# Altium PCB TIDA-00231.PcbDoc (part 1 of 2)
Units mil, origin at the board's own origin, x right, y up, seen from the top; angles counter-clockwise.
Board outline 3780 x 2000 mil, 4 copper layers (Top Layer, L2_GND-PLANE, L3_PWR-PLANE, Bottom Layer), stack 90 mil thick; 180 components, 82 nets, 468 pads, 188 vias.
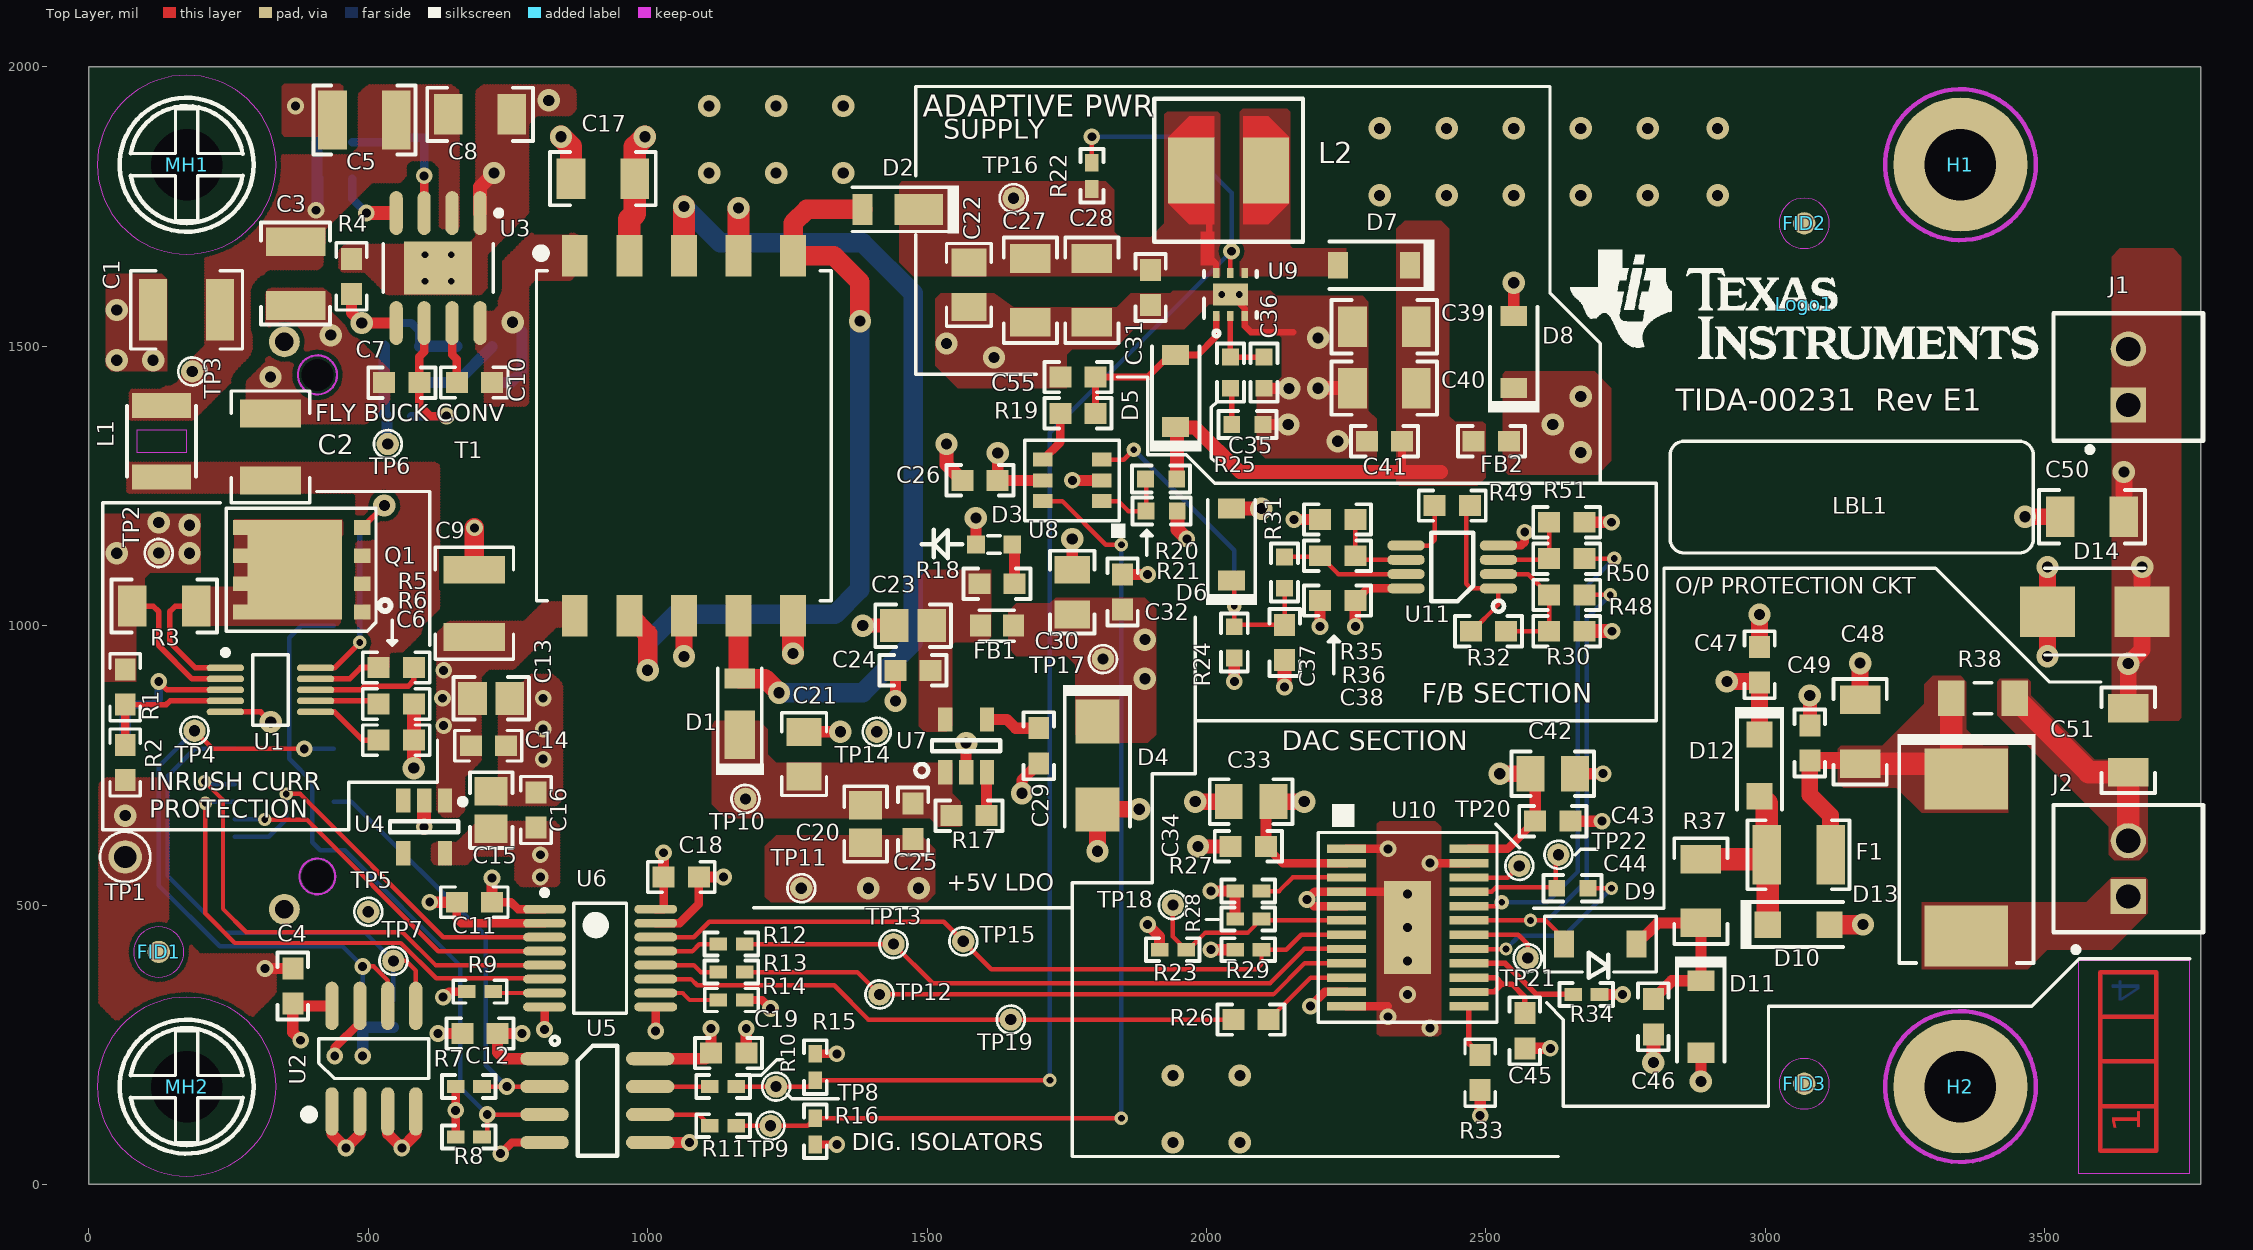
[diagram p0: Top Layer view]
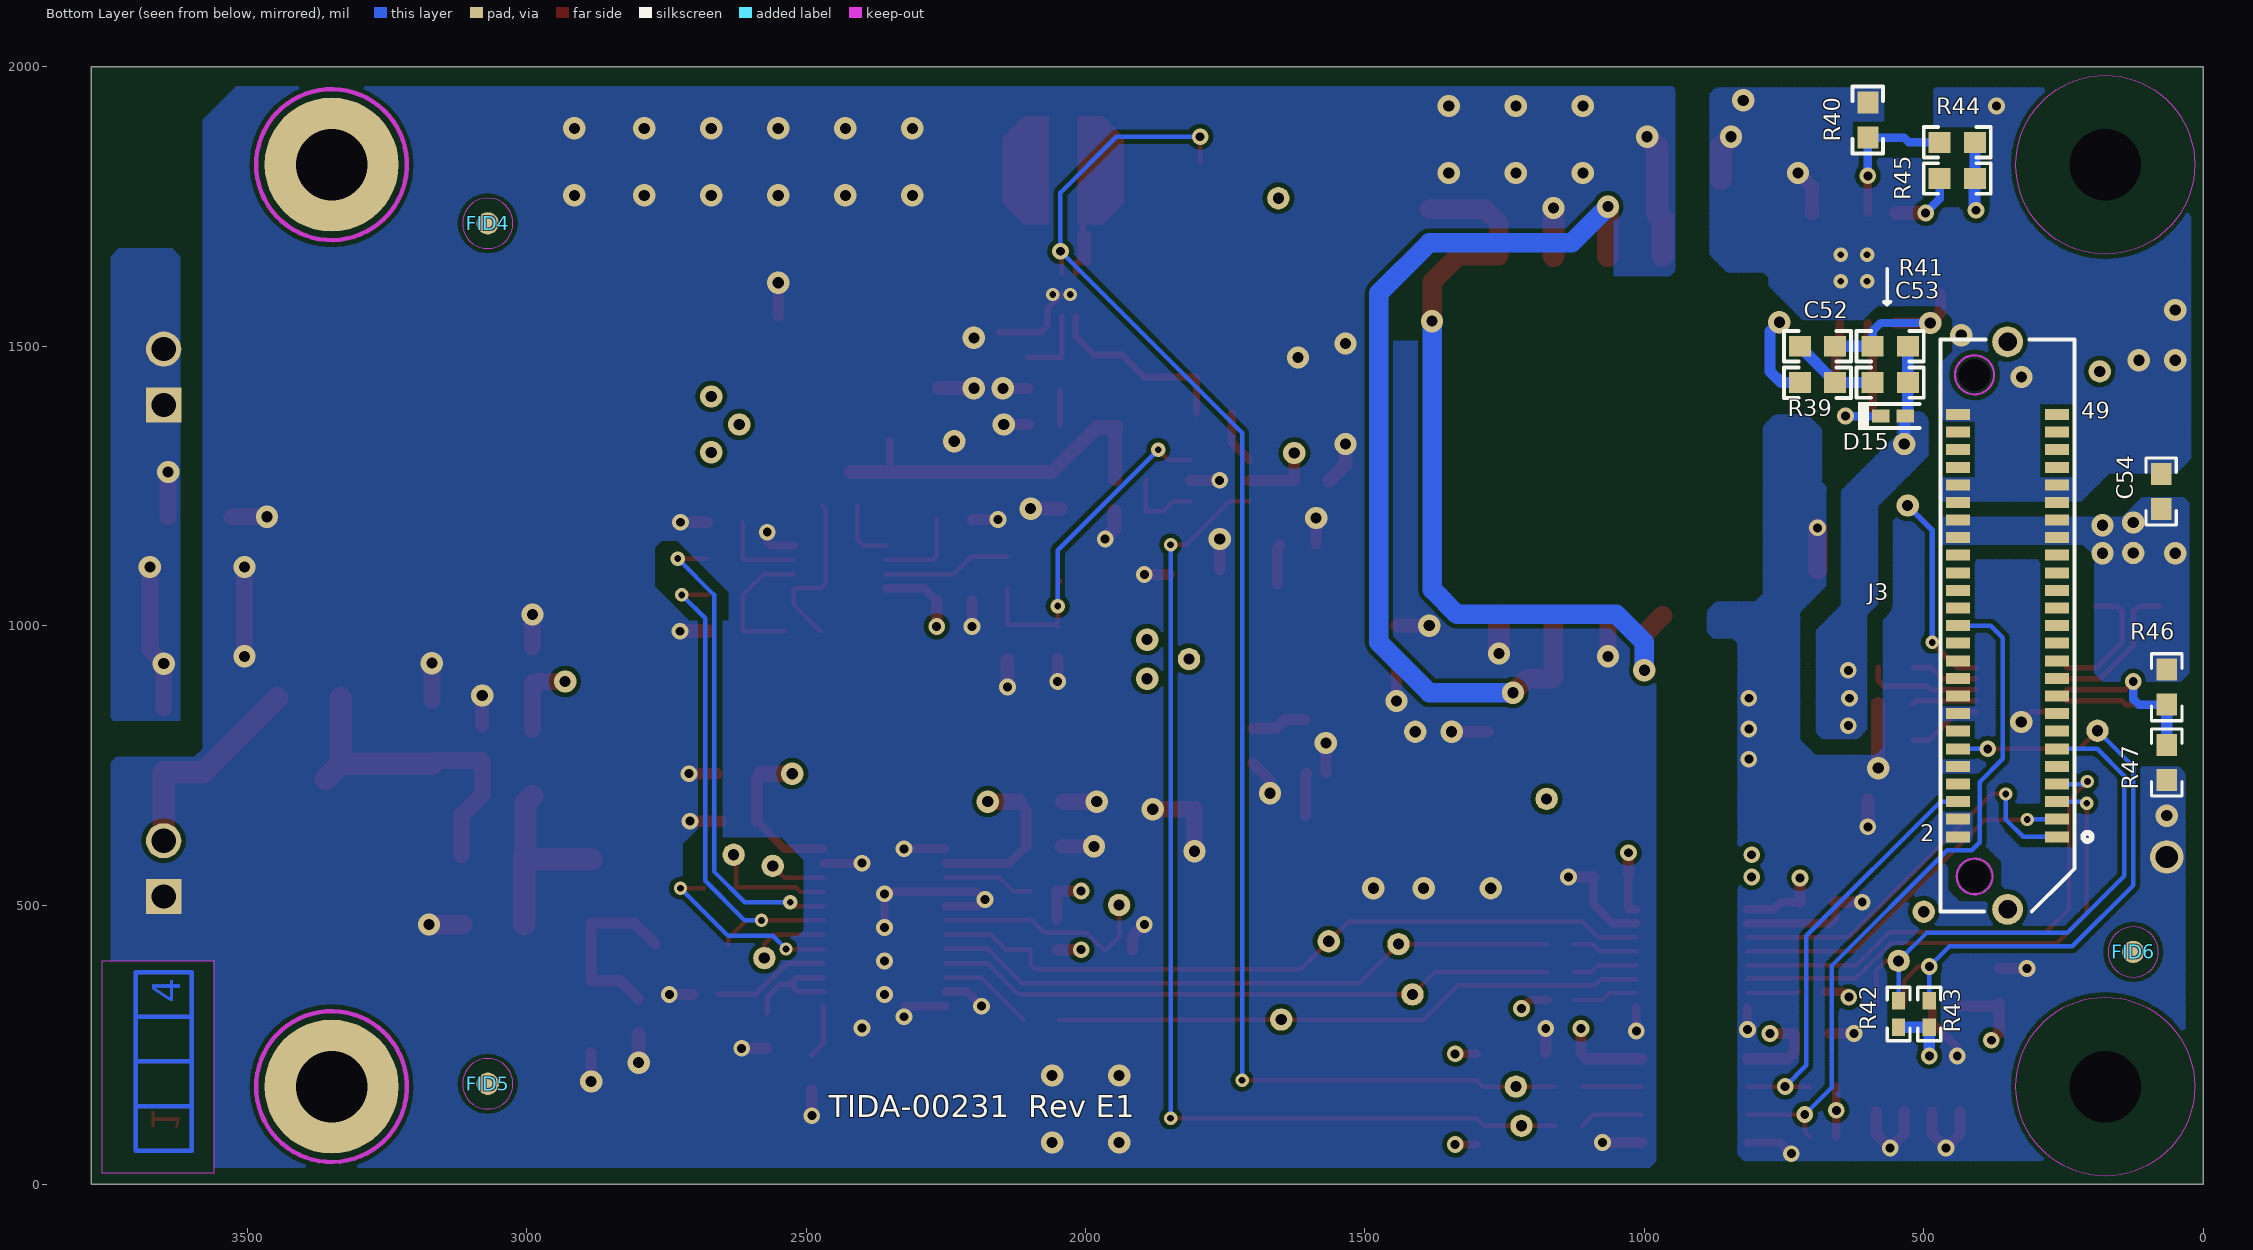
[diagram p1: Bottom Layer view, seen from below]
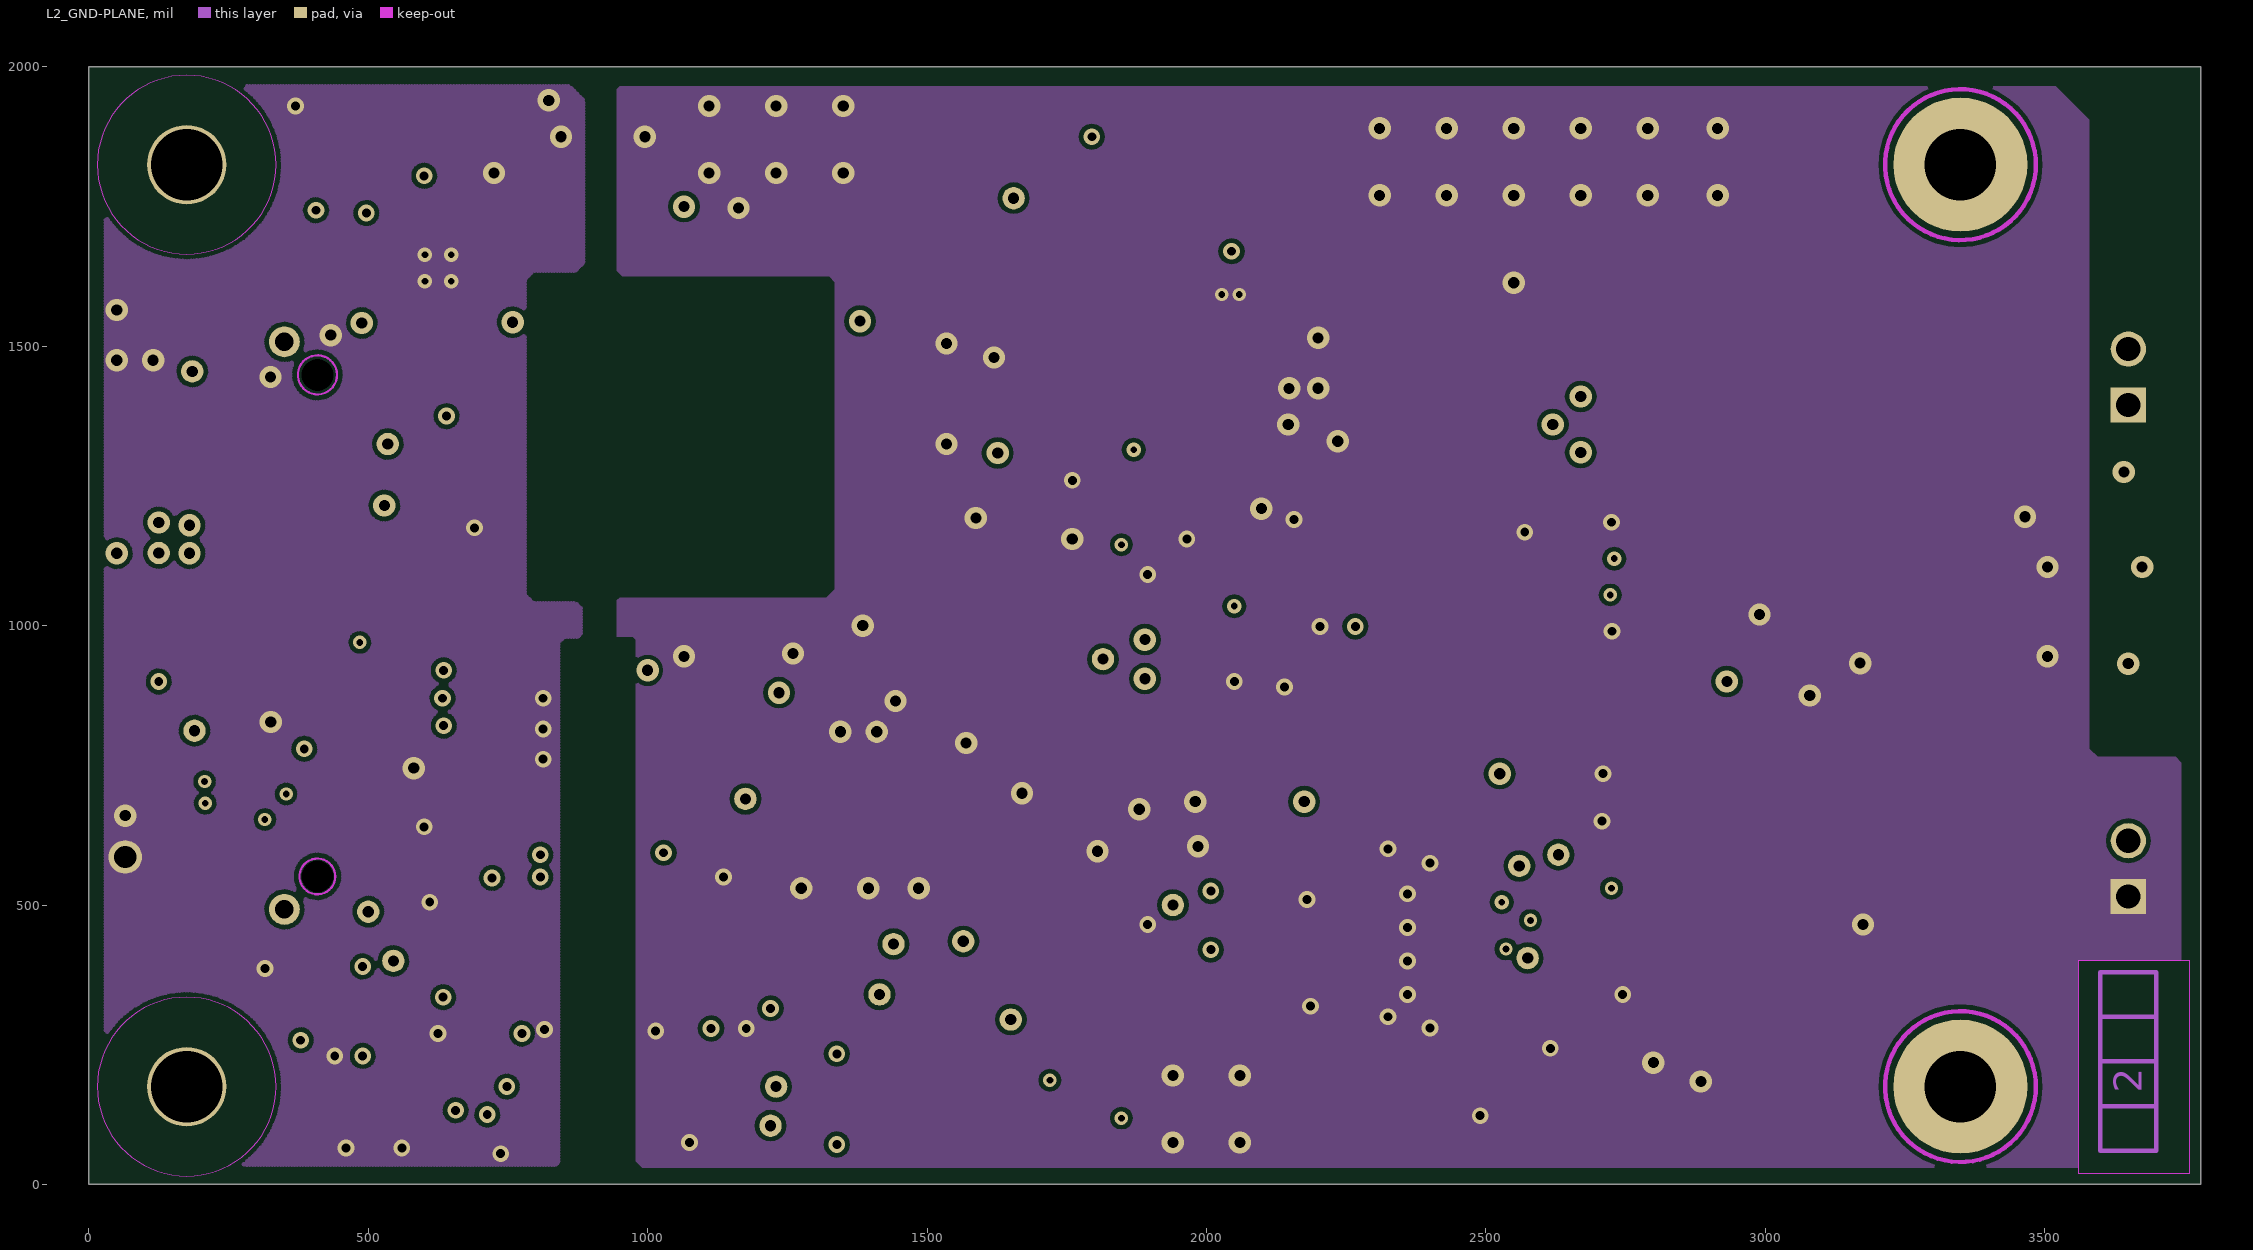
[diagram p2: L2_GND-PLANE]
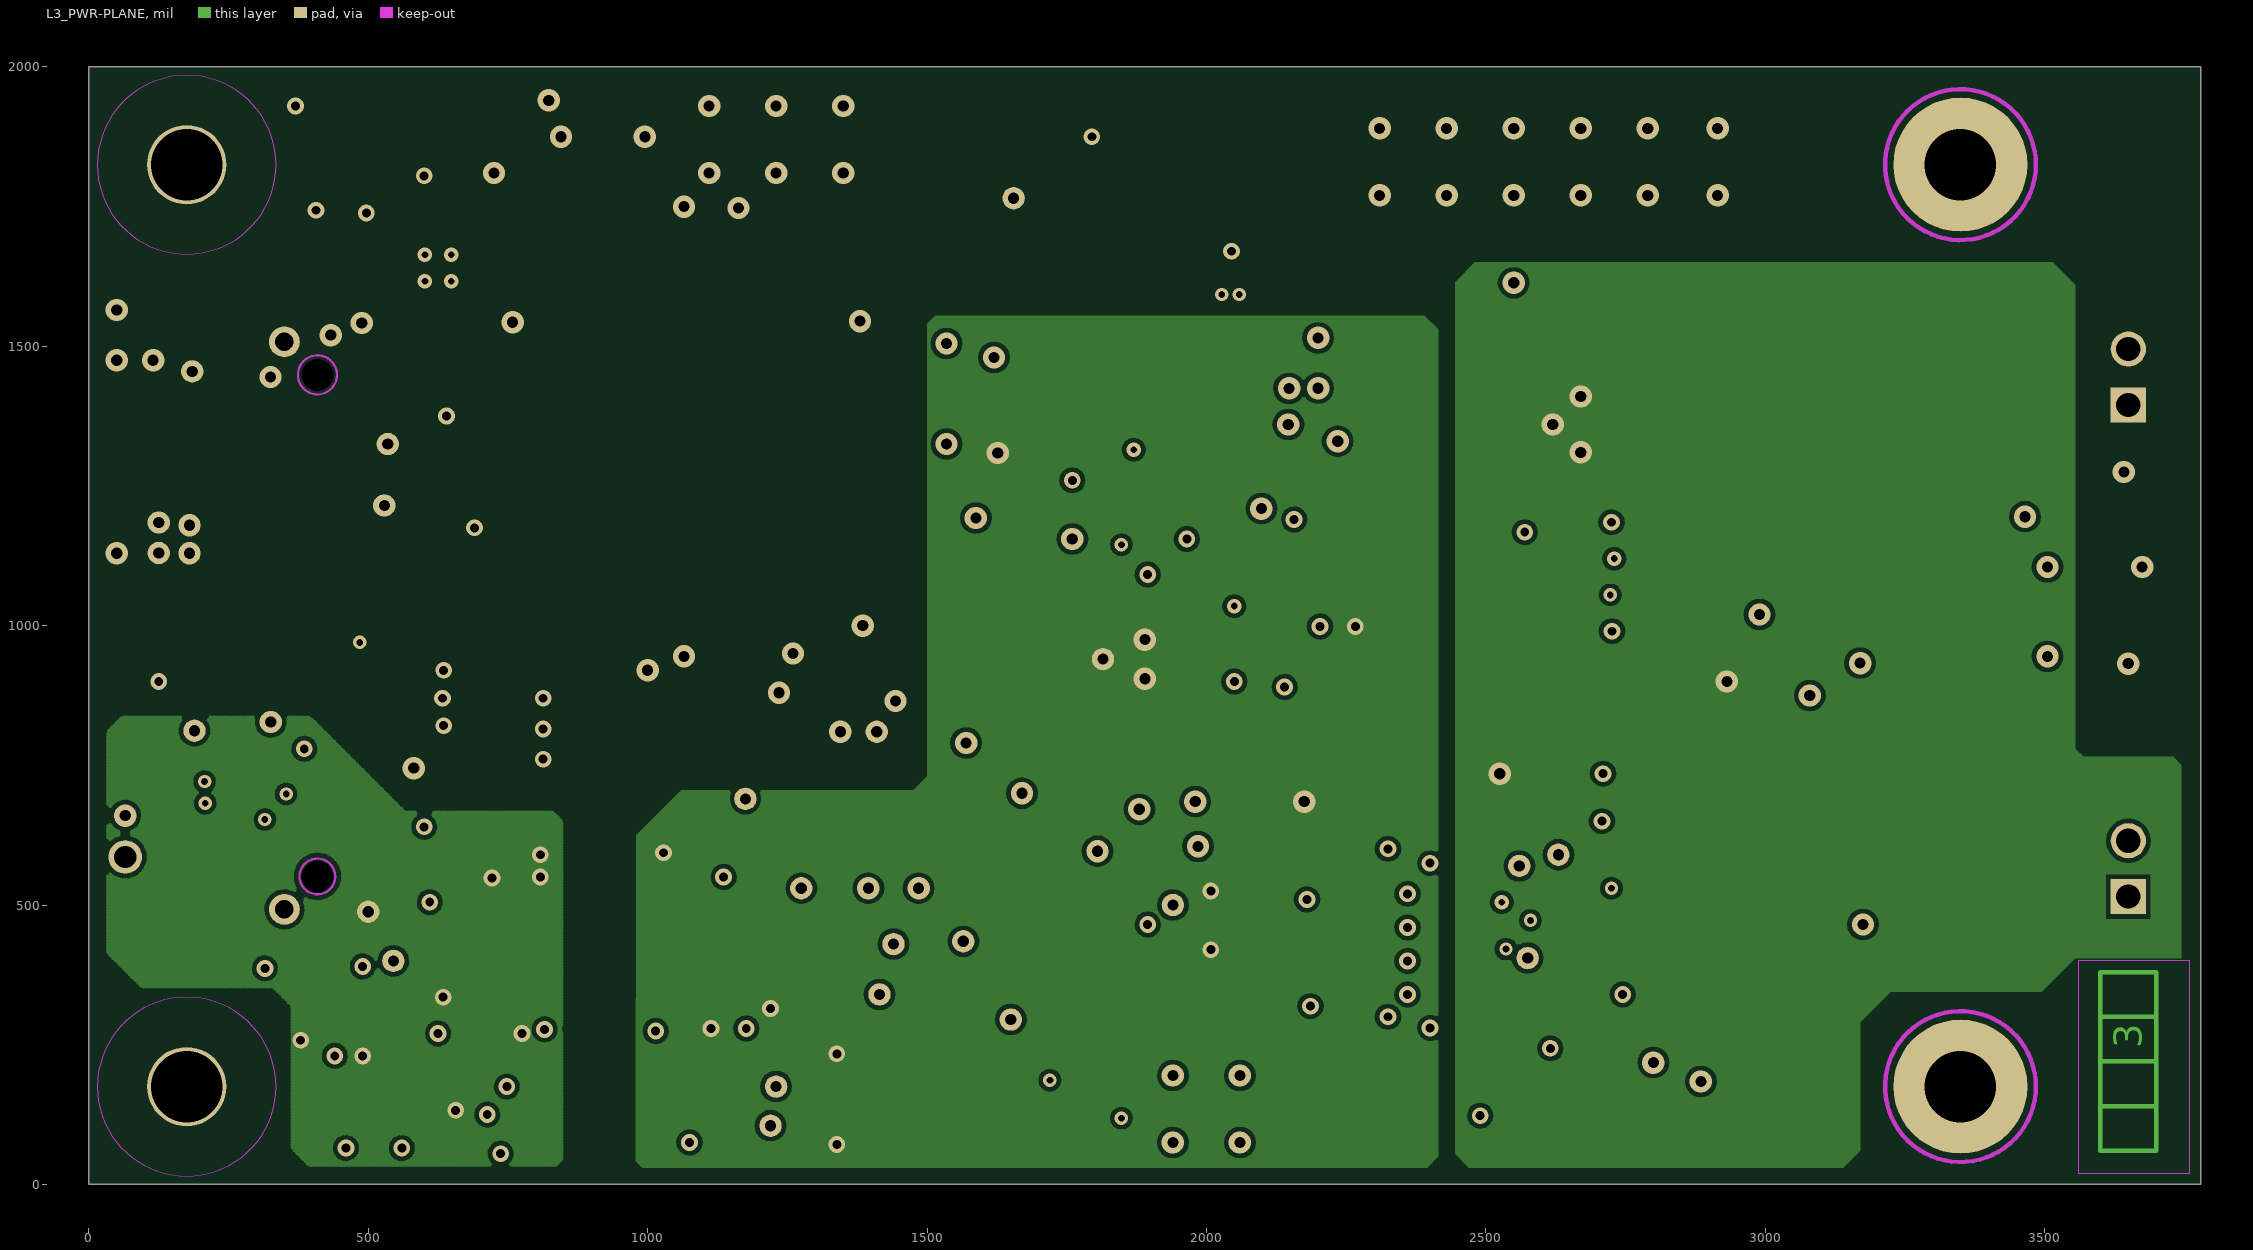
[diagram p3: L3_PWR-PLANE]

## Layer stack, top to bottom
Top Layer: signal copper 1.4
Dielectric: core 59.2, FR-4, Dk 4.8
L2_GND-PLANE: signal copper 1.4
Dielectric: prepreg 12.6, FR-4, Dk 4.8
L3_PWR-PLANE: signal copper 1.4
Dielectric: core 12.6, FR-4, Dk 4.8
Bottom Layer: signal copper 1.4

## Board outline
0,0 0,2000 3780,2000 3780,0

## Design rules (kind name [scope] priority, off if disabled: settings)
AcuteAngle [All] p1: minimum=4.50000000000000E+0001 checktracksonly=FALSE
AssemblyTestPointUsage [All] p1: valid=2
Clearance "U7 AND U9 Pad Class" [(InPadClass('Less Than 7.7')) vs (InPadClass('Less Than 7.7'))] p1: gap=7.8
Clearance "Clearance_Poly to Poly" [InPolygon vs InPolygon] p2: gap=25
Clearance "Clearance_VIA TO VIA" [IsVia vs IsVia] p3: gap=10
Clearance "Clearance_Via to SMD" [IsVia vs IsSMTPin] p4: gap=9
Clearance Clearance_Poly [InPolygon vs IsTrack and IsVia and IsSMTPin and IsThruPin] p5: gap=12
Clearance [All] p6: gap=8
ComponentClearance ComponentClearance_Logo [InComponentClass('Logo')] p1: gap=50 collisioncheckmode=3 verticalgap=10 showdistances=FALSE
ComponentClearance ComponentClearance_ScrewToNut [(HasFootprint('NY PMS 440 0025 PH')) vs (HasFootprint('Keystone_1902C'))] p2: gap=5 collisioncheckmode=3 verticalgap=10 showdistances=FALSE
ComponentClearance ComponentClearance_MountingHoles [InComponentClass('Mounting Holes')] p3: gap=250 collisioncheckmode=3 verticalgap=100000 showdistances=FALSE
ComponentClearance ComponentClearance_SmallPassives [HasFootprint('0201*') or HasFootprint('0402*') or HasFootprint('0508') or HasFootprint('0603*') or HasFootprint('0612') or HasFootprint('0805*') or HasFootprint('0815*') or HasFootprint('0830*') or HasFootprint('1206*') or HasFootprint('1210*') or HasFootprint('1808*') or HasFootprint('1812*') or HasFootprint('1825*') or HasFootprint('2010*') or HasFootprint('2220*') or HasFootprint('2225*') or HasFootprint('2512*') or HasFootprint('2728*') or HasFootprint('3518*') vs HasFootprint('0201*') or HasFootprint('0402*') or HasFootprint('0508') or HasFootprint('0603*') or HasFootprint('0612') or HasFootprint('0805*') or HasFootprint('0815*') or HasFootprint('0830*') or HasFootprint('1206*') or HasFootprint('1210*') or HasFootprint('1808*') or HasFootprint('1812*') or HasFootprint('1825*') or HasFootprint('2010*') or HasFootprint('2220*') or HasFootprint('2225*') or HasFootprint('2512*') or HasFootprint('2728*') or HasFootprint('3518*')] p4: gap=20 collisioncheckmode=3 verticalgap=10 showdistances=FALSE
ComponentClearance ComponentClearance_THtoSMT [IsThruComponent vs IsSMTComponent] p5: gap=100 collisioncheckmode=3 verticalgap=30 showdistances=FALSE
ComponentClearance ComponentClearance_THtoTH [IsThruComponent vs IsThruComponent] p6: gap=118.11 collisioncheckmode=3 verticalgap=30 showdistances=FALSE
ComponentClearance [All] p7: gap=40 collisioncheckmode=3 verticalgap=10 showdistances=FALSE
DiffPairsRouting [All] p1: maxlimit=100 minlimit=10 mostfreqgap=10 maxuncoupledlength=1000
FabricationTestPointUsage TestPointUsage [All] p1: valid=2 allowmultiple=FALSE
FabricationTestpoint Testpoint [All] p1: side=3 testpointundercomponent=TRUE minsize=40 maxsize=100 preferedsize=60 minholesize=0 maxholesize=40 preferedholesize=32 testpointgrid=1 allowsidetop=TRUE allowsidebottom=TRUE usegrid=TRUE gridtolerance=0.01
FanoutControl Fanout_LCC [IsLCC] p1: bgadir=Out bgaviamode=Centered fanoutstyle=Auto fanoutdirection=Alternating viagrid=1 // Fanout_LCC (Default Rule)
FanoutControl Fanout_BGA [IsBGA] p2: bgadir=Out bgaviamode=Centered fanoutstyle=Auto fanoutdirection=Alternating viagrid=1 // Fanout_BGA (Default Rule)
FanoutControl Fanout_Default [All] p4: bgadir=Out bgaviamode=Centered fanoutstyle=Auto fanoutdirection=Alternating viagrid=1 // Fanout_Default (Default Rule)
FanoutControl Fanout_Small [(CompPinCount < 5)] p5: bgadir=Out bgaviamode=Centered fanoutstyle=Auto fanoutdirection=OutThenIn viagrid=1 // Fanout_Small (Default Rule)
HoleSize [All] p1: absolutevalues=TRUE maxlimit=251 minlimit=7.8 maxpercent=80.000 minpercent=20.000
MinimumAnnularRing MinimumAnnularRing_ThermalPadVias [IsVia and InAnyComponent] p1: minimumring=5.91
MinimumAnnularRing [All] p2: minimumring=6
MinimumSolderMaskSliver MinimumSolderMaskSliver_Logo [InComponentClass('Logo') vs InComponentClass('Logo')] p1: minsoldermaskwidth=0.7
MinimumSolderMaskSliver [All] p2: minsoldermaskwidth=3.94
PlaneClearance [All] p1: clearance=16
PlaneConnect [All] p1: planeconnectstyle=Direct reliefexpansion=10 reliefentries=4 reliefconductorwidth=10 reliefairgap=10
PolygonConnect [All] p1: connectstyle=Direct reliefconductorwidth=10 reliefentries=4 polygonreliefangle="90 Angle" airgapwidth=10
RoutingVias RoutingVias_PWR [InNetClass('PWR')] p1: holewidth=20 width=40 viastyle="Through Hole" minholewidth=20 minwidth=40 maxholewidth=20 maxwidth=40
RoutingVias [InNetClass('All Nets')] p2: holewidth=16 width=30 viastyle="Through Hole" minholewidth=8 minwidth=20 maxholewidth=20 maxwidth=40
RoutingVias ThermalPadVias [IsVia and InAnyComponent] p3: holewidth=7.87 width=19.68 viastyle="Through Hole" minholewidth=7.87 minwidth=19.68 maxholewidth=12.99 maxwidth=23.62
SMDToCorner [All] p1: distance=30000
SilkToSilkClearance [All] p1: silktosilkclearance=5
SilkscreenOverComponentPads [All] p1 off: minsilkscreentomaskgap=5
SolderMaskExpansion [All] p1: expansion=2.5
Width Width_PWR [InNetClass('PWR')] p1: maxlimit=100 minlimit=8 preferedwidth=10
Width [All] p2: maxlimit=100 minlimit=6 preferedwidth=8 checkconnectedcopper=TRUE
13 further rules are at their usual default settings.

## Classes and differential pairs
pad class "Less Than 7.7": U1-1 U1-2 U1-3 U1-4 U1-5 U1-6 U1-7 U1-8 U1-9 U1-10 U11-1 U11-2 U11-3 U11-4 U11-5 U11-6 U11-7 U11-8
component class "Pg4 ISO Power Supply, I2C & SPI Isolators": C1 C3 C5 C7 C8 C9 C10 C11 C12 C13 C14 C15 C16 C17 C18 C19 C20 C21 C22 C23 C24 C25 C29 C30 C32 C52 C53 D1 D2 D3 D4 D15 FB1 L1 R4 R7 R8 R9 R10 R11 R12 R13 R14 R15 R16 R17 R18 R39 R40 R41 R44 R45 T1 TP3 TP5 TP6 TP8 TP9 TP10 TP11 TP14 TP16 TP17 U3 U4 U5 U6 U7
component class "Pg3 Interboard conn, HS & EEPROM": C2 C4 C6 C54 J3 Q1 R1 R2 R3 R5 R6 R42 R43 R46 R47 TP1 TP2 TP4 TP7 U1 U2
component class Logo: Logo1
component class "Pg6 Hardware": FID1 FID2 FID3 FID4 FID5 FID6 H1 H2 LBL1 Logo1 MH1 MH2 ZZ1 ZZ2 ZZ3 ZZ4
component class AssemblyNote: ZZ1 ZZ2 ZZ3 ZZ4
component class Label: LBL1
component class "Mounting Holes": H1 H2
component class "Pg5 Analog Output & Adaptive PS": C26 C27 C28 C31 C33 C34 C35 C36 C37 C38 C39 C40 C41 C42 C43 C44 C45 C46 C47 C48 C49 C50 C51 C55 D5 D6 D7 D8 D9 D10 D11 D12 D13 D14 F1 FB2 J1 J2 L2 R19 R20 R21 R22 R23 R24 R25 R26 R27 R28 R29 R30 R31 R32 R33 R34 R35 R36 R37 R38 R48 R49 R50 R51 TP12 TP13 TP15 TP18 TP19 TP20 TP21 TP22 TP39 TP40 TP41 TP42 TP43 TP44 TP46 U8 U9 U10 U11

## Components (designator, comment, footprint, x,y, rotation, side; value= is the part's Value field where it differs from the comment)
C1 "GRM32ER72A225KA35L" 1210#1 175,1565 r180 top (schematic designator C88)
C2 "GRM32ER72A225KA35L" 1210#1 325,1320 r270 top (schematic designator C44)
C3 "GRM32ER71H106KA12L" 1210#2 370,1630 r270 top (schematic designator C136)
C4 "C0603C104K5RACTU" 0603 365,355 r270 top (schematic designator C29)
C5 "GRM32ER72A225KA35L" 1210#2 493,1905 r0 top (schematic designator C10)
C6 "UMK107ABJ474KA-T" 0603 550,795 r0 top (schematic designator C78)
C7 "GRM188R61H105KAALD" 0603 560,1435 r180 top (schematic designator C8)
C8 "GRM31MR72A474KA35L" 1206 700,1915 r180 top (schematic designator C3)
C9 "GMK325AB7106MM-T" 1210#1 690,1040 r270 top (schematic designator C96)
C10 "06031C103JAT2A" 0603 690,1435 r0 top (schematic designator C4)
C11 "C0603C104K5RACTU" 0603 690,505 r0 top (schematic designator C106)
C12 "C0603C104K5RACTU" 0603 700,270 r0 top (schematic designator C133)
C13 "08055C105KAT2A" 0805 720,870 r0 top (schematic designator C17)
C14 "C0603C104K5RACTU" 0603 715,785 r0 top (schematic designator C20)
C15 "0805YD106MAT2A" 0805 720,670 r90 top (schematic designator C105)
C16 "C0603C104K5RACTU" 0603 800,670 r90 top (schematic designator C23)
C17 "202R18W102KV4E" 1206 920,1800 r0 top (schematic designator C36)
C18 "C0603C104K5RACTU" 0603 1060,550 r0 top (schematic designator C68)
C19 "C0603C104K5RACTU" 0603 1145,235 r0 top (schematic designator C134)
C20 "08055C105KAT2A" 0805 1390,645 r270 top (schematic designator C112)
C21 "GRM21BR71E225KA73L" 0805_HV 1280,770 r270 top (schematic designator C24)
C22 "GRM21BR71E225KA73L" 0805_HV 1575,1610 r270 top (schematic designator C6)
C23 "0805YD106MAT2A" 0805 1475,1000 r180 top (schematic designator C87)
C24 "C0603C104K5RACTU" 0603 1475,920 r180 top (schematic designator C18)
C25 "C0603C104K5RACTU" 0603 1475,650 r270 top (schematic designator C86)
C26 "06035C104KAT2A" 0603 1595,1260 r180 top (schematic designator C91)
C27 "GRM31CR61H225KA88L" 1206 1685,1600 r270 top (schematic designator C33)
C28 "GRM31CR61H225KA88L" 1206 1795,1600 r270 top (schematic designator C21)
C29 "C0603C103J5RACTU" 0603 1700,785 r270 top (schematic designator C22)
C30 "C2012X5R1H475K125AB" 0805_HV 1760,1060 r90 top (schematic designator C76)
C31 "06035C104KAT2A" 0603 1900,1605 r270 top (schematic designator C84)
C32 "C0603C104K5RACTU" 0603 1850,1060 r90 top (schematic designator C85)
C33 "C2012X5R1H475K125AB" 0805_HV 2080,685 r0 top (schematic designator C89)
C34 "06035C104KAT2A" 0603 2075,605 r0 top (schematic designator C9)
C35 "06035A470JAT2A" 0603_HV 2073.54,1360 r0 top (schematic designator C99)
C36 "GRM188R71H272KA01D" 0603_HV 2103.05,1452.68 r270 top (schematic designator C97)
C37 "06035C104KAT2A" 0603 2140,970 r270 top (schematic designator C33)
C38 "06035C104KAT2A" 0603 2235,1045 r180 top (schematic designator C78)
C39 "GRM31CR61H225KA88L" 1206 2318.54,1535 r180 top (schematic designator C77)
C40 "GRM31CR61H225KA88L" 1206 2318.54,1425 r180 top (schematic designator C11)
C41 "06035C104KAT2A" 0603 2318.54,1330 r180 top (schematic designator C95)
C42 "C2012X5R1H475K125AB" 0805_HV 2620,735 r180 top (schematic designator C13)
C43 "06035C104KAT2A" 0603 2620,650 r0 top (schematic designator C79)
C44 "06035A101JAT2A" 0603_HV 2655,530 r0 top (schematic designator C93)
C45 "06035C104KAT2A" 0603 2570,275 r90 top (schematic designator C94)
C46 "C0603C103K1RACTU" 0603 2800,300 r270 top (schematic designator C55)
C47 "06035C104KAT2A" 0603 2990,930 r90 top (schematic designator C100)
C48 "202R18W102KV4E" 1206 3170,810 r90 top (schematic designator C93)
C49 "06035C104KAT2A" 0603 3080,790 r90 top (schematic designator C90)
C50 "202R18W102KV4E" 1206 3585,1195 r0 top (schematic designator C30)
C51 "202R18W102KV4E" 1206 3650,795 r90 top (schematic designator C110)
C52 "GRM188R72A104KA35D" 0603 690,1500 r180 bottom (schematic designator C94)
C53 "06031C332JAT2A" 0603 560,1435 r180 bottom (schematic designator C92)
C54 "06031C102MAT2A" 0603 75,1240 r90 bottom (schematic designator C70)
C55 "06035C104KAT2A" 0603 1770,1445 r180 top
D1 "DFLS1200-7" powerDI123 1165,855 r90 top (schematic designator D4)
D2 "DFLS1200-7" powerDI123 1435,1745 r180 top (schematic designator D1)
D3 "LED_LG L29K-G2J1-24-Z" LED0603AA 1620,1145 r0 top (schematic designator D6)
D4 "PTZTE255.6B" SMA 1805,750 r270 top (schematic designator D15)
D5 "MMSZ5258B-7-F" SOD-123 1945,1420 r90 top (schematic designator D8)
D6 "MMSZ5223B-7-F" SOD-123 2045,1145 r90 top (schematic designator D18)
D7 "MBR0540T1G" SOD-123 2300,1645 r180 top (schematic designator D2)
D8 "MMSZ5258B-7-F" SOD-123 2550,1490 r90 top (schematic designator D10)
D9 "D-1N4148" D_SOD123 2705,430 r0 top (schematic designator D14)
D10 "PMEG6020ER,115" SOD-123F 3060,465 r0 top (schematic designator D17)
D11 "MBR0540T1G" SOD-123 2885,300 r270 top (schematic designator D13)
D12 "PMEG6020ER,115" SOD-123F 2990,750 r270 top (schematic designator D16)
D13 "SMCJ28A" SMC 3360,585 r270 top (schematic designator D15)
D14 "SMBJ18CA" DIO_SMB_BIAAAA 3590,1025 r0 top (schematic designator D23)
D15 "SDM10U45-7-F" SOD-523 555,1375 r180 bottom (schematic designator D13)
F1 "0ZCB0005FF2E" 1210#2 3060,590 r180 top
FB1 "1000 OHM" FB0603 1625,1000 r0 top (schematic designator FB3)
FB2 "1000 OHM" 0603 2510,1330 r0 top
FID1 "Fiducial40_80" FID_TOP_40_80BA 125,416 r90 top (schematic designator FID4)
FID2 "Fiducial40_80" FID_TOP_40_80BA 3070,1720 r90 top (schematic designator FID5)
FID3 "Fiducial40_80" FID_TOP_40_80BA 3070,180 r0 top
FID4 "Fiducial40_80" FID_TOP_40_80BA 3070,1720 r180 bottom (schematic designator FID6)
FID5 "Fiducial40_80" FID_TOP_40_80BA 3070,180 r90 bottom (schematic designator FID2)
FID6 "Fiducial40_80" FID_TOP_40_80BA 125,416 r90 bottom (schematic designator FID1)
H1 "NY PMS 440 0025 PH" "NY PMS 440 0025 PH" 3349.53,1825 r0 top (schematic designator H2)
H2 "NY PMS 440 0025 PH" "NY PMS 440 0025 PH" 3349.53,175 r0 top (schematic designator H1)
J1 "282834-2" TEC_282834-2 3650,1445 r90 top (schematic designator J9)
J2 "282834-2" TEC_282834-2 3650,565 r90 top (schematic designator J5)
J3 "ERF8-025-05.0-L-DV-K-TR" CONN_ERF8-025-05_0-L-DV-L-TR 350,1000 r270 bottom locked (schematic designator J10)
L1 "3.3µH" IND_B82422H 130,1330 r90 top
L2 "VLCF5028T-221MR22-2" IND_500X500_280 2040,1815 r90 top
LBL1 "Size: 0.65\" x 0.20 \"" Label_650x200 3155,1230 r0 top
Logo1 "Texas Instruments" TI_Stacked_SolderMask_Small 3070,1575 r0 top
MH1 "MH 3.2MM" MH3.2_H5_W6_KO8_STARHEAD 175,1825 r0 top
MH2 "MH 3.2MM" MH3.2_H5_W6_KO8_STARHEAD 175,175 r0 top (schematic designator MH3)
Q1 "CSD18537NQ5A" TRANS_NexFET_Q5A 380,1100 r180 top
R1 "CRCW060395K3FKEA" 0603 65,890 r90 top (schematic designator R93)
R2 "CRCW06037K15FKEA" 0603 65,755 r90 top (schematic designator R67)
R3 "PRL1632-R020-F-T1" 1206 135,1035 r0 top (schematic designator R45)
R4 "RC0603FR-0727KL" 0603 470,1625 r270 top (schematic designator R7)
R5 "CRCW060310K0JNEA" 0603 550,925 r180 top (schematic designator R58)
R6 "RG1608P-563-B-T5" 0603 550,860 r180 top (schematic designator R69)
R7 "CRCW040210K0JNED" 0402 680,175 r0 top (schematic designator R38)
R8 "CRCW040210K0JNED" 0402 680,85 r180 top (schematic designator R2)
R9 "CRCW040210K0JNED" 0402 700,345 r0 top (schematic designator R36)
R10 "RC0402JR-070RL" 0402 1135,175 r0 top (schematic designator R150)
R11 "RC0402JR-070RL" 0402 1135,105 r0 top (schematic designator R42)
R12 "RC0402JR-070RL" 0402 1150,430 r0 top (schematic designator R151)
R13 "RC0402JR-070RL" 0402 1150,380 r0 top (schematic designator R30)
R14 "CRCW040210K0JNED" 0402 1150,330 r0 top (schematic designator R32)
R15 "CRCW040210K0JNED" 0402 1300,210 r90 top (schematic designator R145)
R16 "CRCW040210K0JNED" 0402 1300,95 r270 top (schematic designator R37)
R17 "CRCW060310K0FKEA" 0603 1575,660 r180 top (schematic designator R101)
R18 "CRCW0603560RJNEA" 0603 1625,1075 r180 top (schematic designator R50)
R19 "CRCW06031K00FKEA" 0603 1770,1380 r180 top (schematic designator R13)
R20 "RT0603BRD07280KL" 0603_HV 1919,1262.46 r0 top (schematic designator R26)
R21 "RT0603BRD0712K1L" 0603_HV 1920,1205 r180 top (schematic designator R128)
R22 "CRCW040210K0JNED" 0402 1795,1805 r270 top (schematic designator R157)
R23 "CRCW04020000Z0ED" 0402 1940,420 r180 top (schematic designator R34)
R24 "RG1608P-4121-B-T5" 0603_HV 2050,970 r90 top (schematic designator R21)
R25 "RT0603DRE077K5L" 0603_HV 2043.05,1452.68 r90 top (schematic designator R33)
R26 "CRCW060310R0FKEA" 0603 2080,295 r0 top (schematic designator R107)
R27 "CRCW040210K0JNED" 0402 2075,525 r180 top (schematic designator R24)
R28 "CRCW040210K0JNED" 0402 2075,475 r180 top (schematic designator R86)
R29 "CRCW040210K0JNED" 0402 2075,420 r180 top (schematic designator R108)
R30 "RC0603FR-0753K6L" 0603 2645,990 r180 top (schematic designator R101)
R31 "RG1608P-512-B-T5" 0603_HV 2140,1095 r270 top (schematic designator R46)
R32 "CRCW06031M00FKEA" 0603 2505,990 r180 top (schematic designator R61)
R33 "RT0603BRB0715KL" 0603 2490,200 r270 top (schematic designator R27)
R34 "CRCW04020000Z0ED" 0402 2680,340 r0 top (schematic designator R110)
R35 "CRCW060310K0JNEA" 0603 2235,1190 r0 top (schematic designator R100)
R36 "RT0603BRD0749R9L" 0603 2235,1125 r180 top (schematic designator R101)
R37 "CRCW120610R0JNEA" 1206 2885,525 r270 top (schematic designator R47)
R38 "MMA02040C1009FB300" MMA0204 3390,870 r0 top (schematic designator R79)
R39 "RT0603BRD0756K2L" 0603 690,1435 r0 bottom (schematic designator R77)
R40 "RC0603FR-074K87L" 0603 600,1905 r270 bottom (schematic designator R81)
R41 "RT0603BRD07196KL" 0603 560,1500 r180 bottom (schematic designator R83)
R42 "CRCW04021K50JNED" 0402 545,305 r90 bottom (schematic designator R99)
R43 "CRCW04021K50JNED" 0402 490,305 r90 bottom (schematic designator R97)
R44 "RT0603BRD0760K4L" 0603 440,1865 r180 bottom (schematic designator R80)
R45 "RC0603FR-0791KL" 0603 440,1800 r180 bottom (schematic designator R6)
R46 "CRCW060371K5FKEA" 0603 65,890 r90 bottom (schematic designator R94)
R47 "CRCW060314K3FKEA" 0603 65,755 r90 bottom (schematic designator R68)
R48 "CRCW06031M00FKEA" 0603 2645,1055 r180 top
R49 "CRCW060310K0JNEA" 0603 2440,1215 r180 top
R50 "CRCW06031M00FKEA" 0603 2645,1120 r180 top
R51 "CRCW060351K0JNEA" 0603 2645,1185 r0 top
T1 "750342178" WURTH_750313995 1065,1340 r0 top locked
TP1 "TP-040_RND" TP1_PD40_D0.5_S50#1 65,586 r90 top (schematic designator TP8)
TP2 "TP-040_RND" TP1_PD40_D0.5_S50#2 125,1130 r180 top (schematic designator TP12)
TP3 "TP1_PD40_D0.5_S50" TP1_PD40_D0.5_S50#2 185,1455 r270 top
TP4 "TP-040_RND" TP1_PD40_D0.5_S50#2 189,812 r90 top (schematic designator TP19)
TP5 "TP1_PD40_D0.5_S50" TP1_PD40_D0.5_S50#2 500,488 r0 top (schematic designator TP7)
TP6 "TP1_PD40_D0.5_S50" TP1_PD40_D0.5_S50#2 535,1325 r0 top (schematic designator TP9)
TP7 "TP-040_RND" TP1_PD40_D0.5_S50#2 545,400 r90 top (schematic designator TP24)
TP8 "TP1_PD40_D0.5_S50" TP1_PD40_D0.5_S50#2 1230,175 r90 top (schematic designator TP5)
TP9 "TP1_PD40_D0.5_S50" TP1_PD40_D0.5_S50#2 1220,105 r90 top (schematic designator TP11)
TP10 "TP1_PD40_D0.5_S50" TP1_PD40_D0.5_S50#2 1175,690 r180 top (schematic designator TP4)
TP11 "TP1_PD40_D0.5_S50" TP1_PD40_D0.5_S50#2 1275,530 r90 top (schematic designator TP17)
TP12 "TP-038" TP1_PD40_D0.5_S50#2 1415,340 r90 top (schematic designator TP16)
TP13 "TP-038" TP1_PD40_D0.5_S50#2 1440,430 r90 top (schematic designator TP43)
TP14 "TP1_PD40_D0.5_S50" TP1_PD40_D0.5_S50#2 1410,810 r0 top (schematic designator TP6)
TP15 "TP-038" TP1_PD40_D0.5_S50#2 1565,435 r90 top (schematic designator TP8)
TP16 "TP1_PD40_D0.5_S50" TP1_PD40_D0.5_S50#2 1655,1765 r0 top (schematic designator TP1)
TP17 "TP1_PD40_D0.5_S50" TP1_PD40_D0.5_S50#2 1815,940 r0 top (schematic designator TP45)
TP18 "TP-038" TP1_PD40_D0.5_S50#2 1940,500 r90 top (schematic designator TP23)
TP19 "TP-038" TP1_PD40_D0.5_S50#2 1650,295 r90 top
TP20 "TP-038" TP1_PD40_D0.5_S50#2 2560,570 r90 top (schematic designator TP39)
TP21 "TP-038" TP1_PD40_D0.5_S50#2 2575,405 r90 top (schematic designator TP42)
TP22 "TP-038" TP1_PD40_D0.5_S50#2 2630,590 r90 top (schematic designator TP16)
U1 "LM5069MM-2/NOPB" MUB10A_N 325,885 r0 top (schematic designator U16)
U2 "AT24C02C-SSHM-B" SOIC-8 510,225 r90 top (schematic designator U19)
U3 "LM5017MRE/NOPB" DDA0008B_N 625,1640 r270 top
U4 "TPS70933DBVT" DBV0005A_N 600,640 r270 top (schematic designator U6)
U5 "ISO7420ED" D0008A_N 910,150 r0 top
U6 "ISO7141CCDBQ" DBQ0016A_N 915,405 r0 top (schematic designator U11)
U7 "TPS70950DBVR" DBV0005A_N 1570,785 r90 top (schematic designator U1)
U8 "TS5A3159DBVR" SOT23-6P 1760,1260 r180 top (schematic designator U5)
U9 "TPS61170DRV" DRV0006A 2043.05,1592.68 r90 top (schematic designator U12)
U10 "DAC8760IPWP" PWP24-DIE84X166 2360,460 r0 top (schematic designator U17)
U11 "OPA2171AIDGKR" DGK0008A_N 2440,1105 r180 top (schematic designator U6)
ZZ1 "This Assembly Note is for PCB labels only" AssemblyNoteLabel 343,2496 r0 top
ZZ2 "These assemblies are ESD sensitive, ESD precautions shall be observed." AssemblyNote 342,2429 r0 top
ZZ3 "These assemblies must be clean and free from flux and all contaminants. Use of no clean flux is not acceptable." AssemblyNote 343,2367 r0 top
ZZ4 "These assemblies must comply with workmanship standards IPC-A-610 Class 2, unless otherwise specified." AssemblyNote 349,2303 r0 top

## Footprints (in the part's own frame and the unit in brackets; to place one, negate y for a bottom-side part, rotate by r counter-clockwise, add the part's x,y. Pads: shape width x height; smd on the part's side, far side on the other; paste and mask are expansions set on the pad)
0402 [mm] "0402 from SM-752 data"
  rect 0.8x0.6 smd: 1(-0.6,0) 2(0.6,0)
  silkscreen extent -1.22,-0.52 1.22,0.52, body extent -0.55,-0.3 0.55,0.3, height 0.6
0603 [mm] "0603 from SM-752 data"
  rect 1x0.95 smd: 1(-0.8,0) 2(0.8,0)
  silkscreen extent -1.52,-0.69 1.52,0.69, body extent -0.87,-0.47 0.87,0.47, height 0.85
0603_HV [mil] "Ernesto recommended land pattern.  26 mil between pads."
  rect 30x30 smd: 1(-28,0) 2(28,0)
  silkscreen extent -52,-24 52,24, body extent -34,-19 34,19, height 33
0805 [mm] "0805 from SM-752 data"
  rect 1.3x1.5 smd: 1(-0.85,0) 2(0.85,0)
  silkscreen extent -1.72,-0.97 1.72,0.97, body extent -1.1,-0.72 1.1,0.72, height 1.1
0805_HV [mil] "0805 with 30mil clearance between pads"
  rect 50x63 smd: 1(-40,0) 2(40,0)
  silkscreen extent -74,-40 74,40, body extent -43,-29 43,29, height 43
1206 [mm] "1206 from SM-752 data"
  rect 1.3x1.85 smd: 1(-1.45,0) 2(1.45,0)
  silkscreen extent -2.4,-1.21 2.4,1.21, body extent -1.7,-0.9 1.7,0.9, height 1.35
1210#1 [mil]
  rect 50x110 smd: 1(60,0) 2(-60,0)
  silkscreen extent -100,-70 100,70
1210#2 [mil] "1210 from SM-752 data"
  rect 51.18x106.3 smd: 1(-57.09,0) 2(57.09,0)
  silkscreen extent -91,-62 91,62, body extent -67,-53 67,53, height 53
AssemblyNote [mil] "Assembly Note"
AssemblyNoteLabel [mil] "Assembly Note for PCB Labels"
CONN_ERF8-025-05_0-L-DV-L-TR [mm] "Samtec 25X2 Header"
  rect 0.5x1.1 smd: 1(9.6,2.25) 2(9.6,-2.25) 3(8.8,2.25) 4(8.8,-2.25) 5(8,2.25) 6(8,-2.25) 7(7.2,2.25) 8(7.2,-2.25) 9(6.4,2.25) 10(6.4,-2.25) 11(5.6,2.25) 12(5.6,-2.25) 13(4.8,2.25) 14(4.8,-2.25) 15(4,2.25) 16(4,-2.25) 17(3.2,2.25) 18(3.2,-2.25) 19(2.4,2.25) 20(2.4,-2.25) 21(1.6,2.25) 22(1.6,-2.25) 23(0.8,2.25) 24(0.8,-2.25) 25(0,2.25) 26(0,-2.25) 27(-0.8,2.25) 28(-0.8,-2.25) 29(-1.6,2.25) 30(-1.6,-2.25) 31(-2.4,2.25) 32(-2.4,-2.25) 33(-3.2,2.25) 34(-3.2,-2.25) 35(-4,2.25) 36(-4,-2.25) 37(-4.8,2.25) 38(-4.8,-2.25) 39(-5.6,2.25) 40(-5.6,-2.25) 41(-6.4,2.25) 42(-6.4,-2.25) 43(-7.2,2.25) 44(-7.2,-2.25) 45(-8,2.25) 46(-8,-2.25) 47(-8.8,2.25) 48(-8.8,-2.25) 49(-9.6,2.25) 50(-9.6,-2.25)
  round 1.4 hole 0.838: MH1(12.9,0) MH2(-12.9,0)
  round 1 hole 1.45 unplated mask+0.508: MH3(11.4,-1.5) MH4(-11.4,-1.5)
  silkscreen extent -13,-3.05 13,3.05, body extent -13.03,-2.8 13.03,2.8, height 5.3
D0008A_N [mm] "SOIC, 8-Leads, Body 4.9x3.9mm, Pitch 1.27mm, IPC Medium Density"
  oval 2.2x0.6 smd: 1(-2.4,1.905) 2(-2.4,0.635) 3(-2.4,-0.635) 4(-2.4,-1.905) 5(2.4,-1.905) 6(2.4,-0.635) 7(2.4,0.635) 8(2.4,1.905)
  silkscreen extent -0.9,-2.5 0.9,2.5, body extent -3,-2.45 3,2.45, height 1.63
D_SOD123 [mil]
  rect 36x48 smd: 1(65,0) 2(-65,0)
  silkscreen extent -21,-60 14,-15
DBQ0016A_N [mm] "SOP, 16-Leads, Body 4.9x3.9mm, Pitch 0.635mm, IPC Medium Density"
  oval 1.95x0.4 smd: 1(-2.525,2.222) 2(-2.525,1.587) 3(-2.525,0.953) 4(-2.525,0.318) 5(-2.525,-0.318) 6(-2.525,-0.953) 7(-2.525,-1.587) 8(-2.525,-2.222) 9(2.525,-2.222) 10(2.525,-1.587) 11(2.525,-0.953) 12(2.525,-0.318) 13(2.525,0.318) 14(2.525,0.953) 15(2.525,1.587) 16(2.525,2.222)
  silkscreen extent -2.65,-2.5 1.2,3.1, body extent -1.99,-2.5 2,2.5, height 1.76
DBV0005A_N [mm] "SOT23, 5-Leads, Body 2.9x1.6mm, Pitch 0.95mm, Lead Span 2.8mm, IPC Medium Density"
  rect 1.1x0.65 smd: 1(-1.2,0.95) 2(-1.2,0) 3(-1.2,-0.95) 4(1.2,-0.95) 5(1.2,0.95)
  silkscreen extent -0.25,-1.55 0.25,1.55, body extent -1.42,-1.46 1.42,1.46, height 1.08
DDA0008B_N [mm] "SOIC, 8-Leads, Body 4.9x3.9mm, Pitch 1.27mm, Exposed Pad, IPC Medium Density"
  oval 2x0.6 smd: 1(-2.5,1.905) 2(-2.5,0.635) 3(-2.5,-0.635) 4(-2.5,-1.905) 5(2.5,-1.905) 6(2.5,-0.635) 7(2.5,0.635) 8(2.5,1.905)
  rect 2.41x3.1 smd: 9(0,0)
  silkscreen extent -2.62,-2.5 1.1,2.88, body extent -2,-2.5 2,2.5, height 1.68
DGK0008A_N [mm] "TSOP, 8-Leads, Body 3x3mm, Pitch 0.65mm, IPC Medium Density"
  oval 1.7x0.45 smd mask+0.05: 1(-2.1,0.975) 2(-2.1,0.325) 3(-2.1,-0.325) 4(-2.1,-0.975) 5(2.1,-0.975) 6(2.1,-0.325) 7(2.1,0.325) 8(2.1,0.975)
  silkscreen extent -0.95,-1.55 0.95,1.55, body extent -2.45,-1.5 2.45,1.5, height 0.94
DIO_SMB_BIAAAA [mm]
  rect 2.5x2.3 smd: 1(-2.15,0) 2(2.15,0)
  silkscreen extent -2.28,-1.97 2.29,1.97
DRV0006A [mm] "SON, 6-Leads, Body 2x2mm, Pitch 0.65mm, Thermal Pad 1.6x1mm, TI Recommended"
  rect 0.45x0.3 smd: 1(-0.975,0.65) 2(-0.975,0) 3(-0.975,-0.65) 4(0.975,-0.65) 5(0.975,0) 6(0.975,0.65)
  rect 1x1.6 smd paste-0.5: 7(0,0)
  silkscreen extent -1.05,-1.2 1.05,1.2, body extent -1.05,-1.05 1.05,1.05, height 0.81
FB0603 [mm]
  rect 0.95x1 smd: 1(-0.75,0) 2(0.75,0)
  silkscreen extent -0.8,-0.7 0.8,0.7
FID_TOP_40_80BA [mil]
  round 40 smd mask+20: 1(0,0)
  Top Layer keep-out region: 45,0 41.57,17.22 31.82,31.82 17.22,41.57 0,45 0,45 -17.22,41.57 -31.82,31.82 -41.57,17.22 -45,0 -45,0 -41.57,-17.22 -31.82,-31.82 -17.22,-41.57 0,-45 0,-45 17.22,-41.57 31.82,-31.82 41.57,-17.22 45,0
IND_500X500_280 [mm] "INDUCTOR POWER 220UH .22A SMD"
  rect 3x2.1 smd: 1(0,1.7) 2(0,-1.7)
  Top Layer region: -2.45,1.8 -2.45,0.65 2.45,0.65 2.45,1.8 1.5,2.75 -1.5,2.75
  Top Layer region: 2.45,-1.8 2.45,-0.65 -2.45,-0.65 -2.45,-1.8 -1.5,-2.75 1.5,-2.75
  silkscreen extent -3.25,-3.38 3.25,3.38, body extent -2.5,-2.65 2.5,2.65, height 2.8
IND_B82422H [mm]
  rect 1.15x2.7 smd: 1(-1.625,0) 2(1.625,0)
  Top Layer keep-out region: -0.508,-1.136 0.508,-1.136 0.508,1.13 -0.508,1.13
  silkscreen extent -1.6,-1.57 1.6,1.57, body extent -1.6,-1.25 1.6,1.25, height 2.4
Label_650x200 [mil] "Thermal Transfer Label"
  silkscreen extent -325,-100 325,100, body extent -326,-101 326,101, height 1
LED0603AA [mil]
  rect 32x32 smd: 1(-32.48,0) 2(32.48,0)
  silkscreen extent -129,-24 11,27
MH3.2_H5_W6_KO8_STARHEAD [mil]
  round 20 / inner round 142 / far side round 20 hole 128 unplated mask+65: 1(0,0)
  Keep-Out Layer region: 160,0 147.82,61.23 113.14,113.14 61.23,147.82 0,160 0,160 -61.23,147.82 -113.14,113.14 -147.82,61.23 -160,0 -160,0 -147.82,-61.23 -113.14,-113.14 -61.23,-147.82 0,-160 0,-160 61.23,-147.82 113.14,-113.14 147.82,-61.23 160,0
  silkscreen extent -120,-120 120,120
MMA0204 [mm] "Vishay Beyschlag"
  rect 1.2x1.6 smd: 1(-1.45,0) 2(1.45,0)
  silkscreen extent -0.4,-0.7 0.4,0.7, body extent -1.8,-0.7 1.8,0.7, height 1.4
MUB10A_N [mm] "TSSOP, 10-Leads, Body 3x3mm, Pitch 0.5mm, IPC Medium Density"
  oval 1.7x0.3 smd: 1(-2.05,1) 2(-2.05,0.5) 3(-2.05,0) 4(-2.05,-0.5) 5(-2.05,-1) 6(2.05,-1) 7(2.05,-0.5) 8(2.05,0) 9(2.05,0.5) 10(2.05,1)
  silkscreen extent -2.17,-1.6 0.8,1.82, body extent -1.6,-1.6 1.6,1.6, height 1.09
"NY PMS 440 0025 PH" [mil] "4-40 nylon screw and mounting hole"
  round 240 hole 128: 1(0,0)
  body extent -130,-130 130,130, height 106
powerDI123 [mm] "Diodes Inc recommended land pattern, document number DS30628 Rev. 6-2"
  rect 2.2x1.4 smd: 1(-1.275,0)
  rect 0.9x1.4 smd: 2(1.275,0)
  silkscreen extent -3.1,-1.09 1.76,1.09, body extent -2.38,-0.97 1.52,0.96, height 1
PWP24-DIE84X166 [mil]
  rect 70x15 smd: 1(-109.3,140.5) 2(-109.3,114.9) 3(-109.3,89.3) 4(-109.3,63.7) 5(-109.3,38.1) 6(-109.3,12.5) 7(-109.3,-13.1) 8(-109.3,-38.7) 9(-109.3,-64.3) 10(-109.3,-89.9) 11(-109.3,-115.5) 12(-109.3,-141.1) 13(109.7,-141.2) 14(109.7,-115.6) 15(109.7,-90) 16(109.7,-64.4) 17(109.7,-38.8) 18(109.7,-13.2) 19(109.7,12.4) 20(109.7,38) 21(109.7,63.6) 22(109.7,89.2) 23(109.7,114.8) 24(109.7,140.5)
  rect 84x166 smd: 25(0,-0.1)
  silkscreen extent -135,180 -95,220
SMA [mm] "Molded Diode, 2-Leads, Body 4.3x2.6mm, IPC Medium Density, based on OnSemi component dimensions and land pattern"
  rect 2x2 smd: 1(-2,0) 2(2,0)
  silkscreen extent -3.66,-1.57 2.79,1.57, body extent -2.6,-1.3 2.6,1.3, height 2.42
SMC [mil] "Molded Diode, 2-Leads, Body 6.9x5.8mm, IPC Medium Density, based on OnSemi component dimensions and land patterns"
  rect 110x150 smd: 1(-140.49,0) 2(140.49,0)
  silkscreen extent -221,-123 189,124, body extent -156,-116 156,116, height 91
SOD-123 [mm] "On Semi recommended land pattern"
  rect 0.915x1.22 smd: 1(-1.637,0) 2(1.637,0)
  silkscreen extent -2.75,-1.17 2.03,1.17, body extent -1.93,-0.9 1.93,0.9, height 1.35
SOD-123F [mm] "NXP recommended land pattern"
  rect 1.2x1.2 smd: 1(-1.4,0) 2(1.4,0)
  silkscreen extent -2.64,-1.12 2.01,1.12, body extent -1.8,-0.85 1.8,0.85, height 1.2
SOD-523 [mm] "NXP Semiconductor recommended land pattern, nominal STEP model"
  rect 0.8x0.6 smd: 1(-0.55,0) 2(0.55,0)
  silkscreen extent -1.6,-0.64 1.2,0.63, body extent -0.8,-0.4 0.8,0.4, height 0.72
SOIC-8 [mm] "duplicate of SO-8.  SOIC, 8-Leads, Body 5.0x4.0mm (max), Pitch 1.27mm, IPC Medium Density"
  oval 2.2x0.6 smd: 1(-2.4,1.905) 2(-2.4,0.635) 3(-2.4,-0.635) 4(-2.4,-1.905) 5(2.4,-1.905) 6(2.4,-0.635) 7(2.4,0.635) 8(2.4,1.905)
  silkscreen extent -0.9,-2.5 0.9,2.5, body extent -3,-2.45 3,2.45, height 1.63
SOT23-6P [mil]
  rect 35x25 smd: 1(-52.5,37) 2(-52.5,0) 3(-52.5,-37) 4(52.5,-37) 5(52.5,0) 6(52.5,37)
  silkscreen extent -95,77 -70,102
TEC_282834-2 [mm] "TEC"
  rect 1.6x1.6 hole 1.1: 1(-1.27,0)
  round 1.6 hole 1.1: 2(1.27,0)
  silkscreen extent -3.4,-3.4 2.9,3.4, body extent -2.77,-3.25 2.77,3.25, height 10.01
TI_Stacked_SolderMask_Small [mil]
  silkscreen extent -418,-98 418,98
TP1_PD40_D0.5_S50#1 [mil]
  round 60 hole 40: 1(0,0)
  silkscreen extent -45,-45 45,45
TP1_PD40_D0.5_S50#2 [mil]
  round 40 hole 20: 1(0,0)
  silkscreen extent -25,-25 25,25
TRANS_NexFET_Q5A [mm] "TI recommended land pattern (nominal) M0139-01"
  rect 0.75x0.675 smd: 1(-2.776,1.917) 2(-2.776,0.639) 3(-2.776,-0.639) 4(-2.776,-1.917)
  rect 0.655x0.675 smd: 5(2.776,-1.917) 6(2.776,-0.639) 7(2.776,0.639) 8(2.776,1.917)
  rect 4.295x4.51 smd paste-2.2: 9(0.301,0)
  silkscreen extent -3.4,-2.8 3.4,2.8, body extent -3.05,-2.5 3.05,2.5, height 1.11
WURTH_750313995 [mm] "WURTH"
  rect 1.17x1.88 smd: 1(-4.96,8.18) 2(-2.48,8.18) 3(0,8.18) 4(2.48,8.18) 5(4.96,8.18) 6(4.96,-8.18) 7(2.48,-8.18) 8(0,-8.18) 9(-2.48,-8.18) 10(-4.96,-8.18)
  silkscreen extent -6.7,-7.5 6.7,8.5, body extent -6.73,-8.9 6.73,8.9, height 12.7

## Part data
C1 C2 C5: "CAP, CERM, 2.2uF, 100V, +/-10%, X7R, 1210"
C3: "CAP, CERM, 10uF, 50V, +/-10%, X7R, 1210"
C4 C11 C12 C14 C16 C18 C19 C24 C25 C26 C31 C32 C34 C37 C38 C41 C43 C45 C47 C49 C55: "CAP, CERM, 0.1uF, 50V, +/-10%, X7R, 0603"
C6: "CAP, CERM, 0.47uF, 50V, 10%, X5R, 0603"
C7: "CAP, CERM, 1uF, 50V, +/-10%, X5R, 0603"
C8: "CAP, CERM, 0.47uF, 100V, +/-10%, X7R, 1206"
C9: "CAP, CERM, 10uF, 35V, +/-20%, X7R, 1210"
C10: "CAP, CERM, 0.01uF, 100V, +/-5%, X7R, 0603"
C13 C20: "CAP, CERM, 1uF, 50V, +/-10%, X7R, 0805"
C15 C23: "CAP, CERM, 10uF, 16V, +/-20%, X5R, 0805"
C17 C48 C50 C51: "CAP, CERM, 1000pF, 2KV 10% X7R 1206"
C21 C22: "CAP, CERM, 2.2uF, 25V, +/-10%, X7R, 0805"
C27 C28 C39 C40: "CAP, CERM, 2.2uF, 50V, +/-10%, X5R, 1206"
C29: "CAP, CERM, 0.01uF, 50V, +/-5%, X7R, 0603"
C30 C33 C42: "CAP, CERM, 4.7uF, 50V, +/-10%, X5R, 0805"
C35: "CAP, CERM, 47pF, 50V, +/-5%, C0G/NP0, 0603"
C36: "CAP, CERM, 2700pF, 50V, +/-10%, X7R, 0603"
C44: "CAP, CERM, 100pF, 50V, +/-5%, C0G/NP0, 0603"
C46: "CAP, CERM, 0.01uF, 100V, +/-10%, X7R, 0603"
C52: "CAP, CERM, 0.1uF, 100V, +/-10%, X7R, 0603"
C53: "CAP, CERM, 3300pF, 100V, +/-5%, X7R, 0603"
C54: "CAP, CERM, 1000pF, 100V, +/-20%, X7R, 0603"
D1 D2: "Diode, Schottky, 200V, 1A, PowerDI123"
D3: "LED SmartLED Green 570NM"
D4: "DIODE ZENER 5.9V 1W PMDS"
D5 D8: "Diode, Zener, 36V, 500mW, SOD-123"
D6: "Diode, Zener, 2.7V, 500mW, SOD-123"
D7 D11: "Diode, Schottky, 40V, 0.5A, SOD-123"
D9: "Diode, Signal, 300-mA, 75-V, 350-mW"
D10 D12: library part PMEG6010CEH,115, "DIODE SCHOTTKY 60V 2A SOD123W"
D13: "Diode, TVS, Uni, 28V, 1500W, SMC"
D14: "TVS 18 VOLT 600 WATT BI-DIR SMB"
D15: "Diode, Schottky, 45V, 0.1A, SOD-523"
F1: library part 37215000001, "PTC RESTTBLE 0.05A 60V CHIP 1210"
FB1 FB2: library part MMZ1608B102C, "FERRITE CHIP 1000 OHM 300MA 0603"
FID1 FID2 FID3 FID4 FID5 FID6: library part Fiducial40_0
H1 H2: "Machine Screw, Round, #4-40 x 1/4, Nylon, Philips panhead"
J1 J2: "Terminal Block, 2x1, 2.54mm, TH"
J3: "Receptacle, 0.8mm, 25x2, SMT"
L1: library part IND_ELJEA_SERIES, "Inductor, Chip, ±10%"
L2: "INDUCTOR POWER 220UH .22A SMD"
LBL1: library part THT-14-423-10, "Thermal Transfer Printable Labels, 0.650\" W x 0.200\" H - 10,000 per roll"
Logo1: library part TI_Logo, "Texas Instrument Corporate Signature"
MH1 MH2: library part "MH 3_0.5MM", "Mountin hole, NPTH Drill 3.2mm"
Q1: "MOSFET, N-CH, 60V, 50A, SON 5x6mm"
R1: "RES, 95.3k ohm, 1%, 0.1W, 0603"
R2: "RES, 7.15k ohm, 1%, 0.1W, 0603"
R3: "RES, 0.02 ohm, 1%, 1W, 1206"
R4: "RES, 27.0k ohm, 1%, 0.1W, 0603"
R5 R35 R49: "RES, 10k ohm, 5%, 0.1W, 0603"
R6: "RES, 56.0k ohm, 0.1%, 0.1W, 0603"
R7 R8 R9 R14 R15 R16 R22 R27 R28 R29: "RES, 10k ohm, 5%, 0.063W, 0402"
R10 R11 R12 R13 R23 R34: "RES, 0 ohm, 5%, 0.063W, 0402"
R17: "RES, 10.0k ohm, 1%, 0.1W, 0603"
R18: "RES, 560 ohm, 5%, 0.1W, 0603"
R19: "RES, 1.00k ohm, 1%, 0.1W, 0603"
R20: "RES, 280k ohm, 0.1%, 0.1W, 0603"
R21: "RES, 12.1k ohm, 0.1%, 0.1W, 0603"
R24: "RES, 4.12k ohm, 0.1%, 0.1W, 0603"
R25: "RES, 7.50k ohm, 0.5%, 0.1W, 0603"
R26: "RES, 10.0 ohm, 1%, 0.1W, 0603"
R30: "RES, 53.6k ohm, 1%, 0.1W, 0603"
R31: "RES, 5.10k ohm, 0.1%, 0.1W, 0603"
R32 R48 R50: "RES, 1.00Meg ohm, 1%, 0.1W, 0603"
R33: "RES, 15k ohm, 1/10W 0.1% 0603"
R36: "RES, 49.9 ohm, 0.1%, 0.1W, 0603"
R37: "RES, 10 ohm, 5%, 0.25W, 1206"
R38: library part MMA02040C1000FB300, "RES 10 OHM .4W 1% 0204 MELF"
R39: "RES, 56.2k ohm, 0.1%, 0.1W, 0603"
R40: "RES, 4.87k ohm, 1%, 0.1W, 0603"
R41: "RES, 196k ohm, 0.1%, 0.1W, 0603"
R42 R43: "RES, 1.5k ohm, 5%, 0.063W, 0402"
R44: "RES, 60.4k ohm, 0.1%, 0.1W, 0603"
R45: "RES, 91.0k ohm, 1%, 0.1W, 0603"
R46: "RES, 71.5k ohm, 1%, 0.1W, 0603"
R47: "RES, 14.3k ohm, 1%, 0.1W, 0603"
R51: "RES, 51k ohm, 5%, 0.1W, 0603"
T1: library part 750313995, "Transformer, 50uH, SMT"
TP1 TP2 TP4 TP7 TP12 TP13 TP15 TP18 TP19 TP20 TP21 TP22: "Test Point 40mil pad 20mil drill"
TP3 TP5 TP6 TP8 TP9 TP10 TP11 TP14 TP16 TP17: library part TP-040_RND, "Test Point 40mil pad 20mil drill"
U1: "Positive High Voltage Hot Swap / Inrush Current Controller with Power Limiting, 10-pin MSOP, Pb-Free"
U2: "IC, EEPROM, 2KBIT, 1MHZ, SOIC-8"
U3: "100V, 600mA Constant On-Time Synchronous Buck Regulator, DDA0008B"
U4: "IC REG LDO 3.3V 0.15A SOT23-5"
U5: "50 Mbps Low-Power Dual Channels Digital Isolator, 3.3 V / 5 V, -40 to +125 degC, 8-pin SOIC (D), Green (RoHS & no Sb/Br)"
U6: "4242-VPK Small-Footprint and Low-Power Quad Channels Digital Isolators, DBQ0016A"
U7: "IC REG LDO 5V 0.15A SOT23-5"
U8: "IC, 1 Ohm SPDT Analog Switch"
U9: "1.2A High Voltage Boost Converter in 2x2mm QFN Package, DRV0006A"
U10: "1-Channel, 16-Bit, Programmable Current/Voltage Output DAC for 4-20mA Current Loop Applications"
U11: "Low Power, RRO, General Purpose Operational Amplifier in MicroPackage, 2.7 to 36 V, -40 to 125 degC, 8-pin SOP (DGK0008A), Green (RoHS & no Sb/Br)"
ZZ1: library part AssemblyNoteLabel
ZZ2 ZZ3 ZZ4: library part AssemblyNote

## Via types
v1: diameter 40, hole 20, Top Layer to Bottom Layer, tented both sides, 92 vias
v2: diameter 30, hole 16, Top Layer to Bottom Layer, tented both sides, 74 vias
v3: diameter 24, hole 12, Top Layer to Bottom Layer, tented both sides, 14 vias
v4: diameter 26, hole 12, Top Layer to Bottom Layer, tented both sides, 4 vias
v5: diameter 25.98, hole 12, Top Layer to Bottom Layer, tented both sides, 4 vias

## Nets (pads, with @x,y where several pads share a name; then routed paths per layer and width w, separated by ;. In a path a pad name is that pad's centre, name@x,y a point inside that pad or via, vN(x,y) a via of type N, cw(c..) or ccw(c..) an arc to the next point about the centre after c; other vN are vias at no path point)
9.3V_NON_ISO: C9.1 C13.1 C14.1 C53.2 D15.2 R41.2 T1.10 TP6.1 U4.1 | length 168.5
  Bottom Layer w20: D15.2@528.5,1379.84 C53.2@528.5,1435 R41.2@528.5,1500 ; TP6.1@533.35,1326.65 D15.2@533.35,1375
  other v2: 635,821 633,870 635,920
+3.3V_NON_ISO: C4.2 C11.2 C12.2 C15.1 C16.1 R7.1 R8.2 R9.1 R42.1 R43.1 TP5.1 U2.8 U4.5 U5.1 U6.1 | length 688.9
  Top Layer w15: v2(634,335) 644,345 R9.1@676.38,345 ; R8.2@656.38,85 v2(656.38,132.62) R7.1@656.38,175 ; C11.2@721.5,505 755.5,505 768,492.5 U6.1@815.59,492.5
  Top Layer w20: C4.2@365,323.5 365,272 v2(379,258) ; C4.2@369.02,319.49 U2.8@435,319.49 ; C11.2@721.5,505 v2(721.5,548.5) ; v2(775.18,270) C12.2@731.5,270 731.5,236.5 743,225 U5.1@815.51,225
  Bottom Layer w20: v2(490,230) R43.1@490,281.38 R42.1@545,281.38
  other v2: 808,550 808,590
+5V_ISO: C18.1 C19.1 C26.1 C30.1 C32.1 C33.2 C34.2 C38.1 D4.1 FB1.2 R14.2 R15.2 R16.2 R27.2 R28.2 R29.2 TP17.1 U5.8 U6.16 U8.5 U10.2 U11.8 | length 1112.4
  Top Layer w15: U6.16@1014.41,492.5 1028.5,492.5 C18.1@1028.5,550 ; R14.2@1173.62,330 1205,330 v2(1220,315) ; R16.2@1300,71.38 v2(1338.62,71.38) ; R15.2@1300,233.62 v2(1338.62,233.62) ; C34.2@2106.5,605 2136.6,574.9 U10.2@2250.7,574.9 ; C38.1@2266.5,1045 2288.11,1066.61 U11.8@2357.32,1066.61
  Top Layer w20: U5.8@1004.49,225 1103.5,225 C19.1@1113.5,235 v2(1113.5,279) ; C18.1@1028.5,550 v2(1028.5,593.5) ; v1(1626.5,1309) C26.1@1626.5,1260 U8.5@1707.5,1260 ; v2(2008,420) R29.2@2051.38,420 ; v2(2008,525) R27.2@2051.38,525 R28.2@2051.38,475 ; C34.2@2106.5,605 2106.5,671.5 C33.2@2120,685 ; v2(2266.5,998.5) C38.1@2266.5,1045
  Top Layer w30: C33.2@2120,685 v1(2175,685)
  other v1: 1890,905 1890,975
+6V_ISO: C20.1 C21.2 C25.1 D1.1 R17.2 TP10.1 U7.1
+12V_ISO: C22.1 C27.1 C28.1 C31.1 D2.1 L2.1 R22.2 TP16.1 U9.6 | length 94.1
  Top Layer w11: 2005,1720 2005,1660 2017.46,1647.54 U9.6@2017.46,1631.07
+24VDC: C54.1 J3.35 J3.36 J3.37 J3.38 R1.2 R3.1 R46.2 TP2.1 U1.2 | length 255.8
  Top Layer w10: R3.1@77.91,1035 115,1035 125,1025 125,964.54 184.86,904.69 U1.2@244.29,904.69
  other v1: 50,1129.68 180,1129.68 180,1179.68 125,1184.68
+24VDC_LIMIT: C2.1 L1.1 Q1.1 Q1.2 Q1.3 R5.2 U1.9 | length 121.2
  Top Layer w10: U1.9@405.71,904.69 466.69,904.69 487,925 R5.2@518.5,925
/ALARM: J3.6 R7.2 U5.2 | length 768.5
  Top Layer w8: R7.2@703.62,175 v2(748,175) U5.2@815.51,175
  Bottom Layer w8: J3.6@438.58,685.04 469.96,685.04 710,445 710,213 v2(748,175)
/CS0: J3.1 U6.3 | length 718.9
  Top Layer w8: v3(353,698.74) 378.08,698.74 634.32,442.5 U6.3@815.59,442.5
  Bottom Layer w8: J3.1@261.42,622.05 322.05,622.05 353,653 v3(353,698.74)
AOUT0: C51.1 J2.2 R38.2 | length 380.5
  Top Layer w40: R38.2@3447.09,870 3579.17,737.91 C51.1@3650,737.91 J2.2@3650,615
EVM_ID_SCL: J3.12 R43.2 TP4.1 U2.6 | length 1153.7
  Top Layer w8: TP4.1@189,812 221.47,779.53 v2(385.47,779.53) ; v2(490,390) 509.75,390 535,364.75 U2.6@535,319.49
  Bottom Layer w8: TP4.1@189,812 125,748 125,535 234,426 454,426 v2(490,390) R43.2@490,328.62 ; v2(385.47,779.53) J3.12@438.58,779.53
EVM_ID_SDA: J3.11 R42.2 TP7.1 U2.5 | length 968.2
  Top Layer w8: TP7.1@545,400 567.63,400 585,382.63 U2.5@585,319.49
  Bottom Layer w8: J3.11@261.42,779.53 189.53,779.53 141,731 141,552 243,450 495,450 TP7.1@545,400 R42.2@545,328.62
FB_CTRL: R11.2 R16.1 TP9.1 U8.6 | length 1894.2
  Top Layer w8: R11.2@1158.62,105 TP9.1@1220,105 1286.38,105 R16.1@1300,118.62 v3(1848,118.62) ; U8.6@1707.5,1223 1742,1223 1820,1145 v3(1848,1145)
  Bottom Layer w8: v3(1848,118.62) v3(1848,1145)
FET_FB: C37.1 D6.1 R24.2 R31.2 U8.3 | length 661.1
  Top Layer w8: U8.3@1812.5,1297 1852,1297 v4(1870,1315) ; D6.1@2045,1080.53 2050,1075.53 v4(2050,1035) R24.2@2050,998 2053.5,1001.5 C37.1@2140,1001.5 R31.2@2140,1067
  Bottom Layer w8: v4(1870,1315) 2050,1135 v4(2050,1035)
FET_P: R50.1 U10.20 | length 861.4
  Top Layer w8: U10.20@2469.7,498 2521.59,498 v4(2528.59,505) ; R50.1@2676.5,1120 v4(2730,1120)
  Bottom Layer w8: v4(2528.59,505) 2610,505 2665,560 2665,1055 v4(2730,1120)
GND: C1.1 C2.2 C3.2 C4.1 C5.1 C6.2 C7.2 C8.1 C9.2 C11.1 C12.1 C13.2 C14.2 C15.2 C16.2 C17.1 C54.2 J3.2 J3.4 J3.10 J3.16 J3.39 J3.40 J3.41 J3.42 J3.50 R2.1 R4.1 R6.1 R40.1 R47.1 TP1.1 U1.5 U2.1 U2.2 U2.3 U2.4 U2.7 U3.1 U3.9 U4.2 U5.4 U6.2 U6.8 | length 1361
  Top Layer w10: U1.5@244.29,845.63 307.41,845.63 v1(325.52,827.52)
  Top Layer w15: v2(440,230) 440,245 485,290 U2.7@485,319.49 ; C11.1@658.5,505 658.5,475.3 666.3,467.5 U6.2@815.59,467.5 ; v2(737,55) 757,75 U5.4@815.51,75 ; v2(815.59,277.41) U6.8@815.59,317.5
  Top Layer w20: v2(315,386.5) C4.1@365,386.5 ; U2.1@435,130.51 435,90 v2(460,65) 485,90 U2.2@485,130.51 ; U2.3@535,130.51 535,90 v2(560,65) 585,90 U2.4@585,130.51 ; v2(610,505) C11.1@658.5,505 ; v2(624.82,270) C12.1@668.5,270
  Top Layer w25: v1(581.5,745) C6.2@581.5,795 R6.1@581.5,860 ; v2(600,640) U4.2@600,687.24 ; U3.1@700,1738.43 700,1785 v1(725,1810)
  Top Layer w35: C9.2@690,1100 v2(690,1175)
  Top Layer w40: v1(845,1875) 862.91,1857.09 C17.1@862.91,1800
  other v1: 65,660 325,1445 50,1475 115,1475 433,1520 50,1565 823,1940
  other v2: 813,761 813,815 813,870 370,1930
  other v5: 601.38,1616.38 648.62,1616.38 601.38,1663.62 648.62,1663.62
GND_EARTH: C50.2 C51.2 D14.2 J1.1 J1.2 | length 343.1
  Top Layer w30: C50.2@3642.09,1195 v1(3642.09,1275) ; C51.2@3650,852.09 v1(3650,932.09) 3674.65,956.73 D14.2@3674.65,1025 v1(3674.65,1105)
HART0: TP21.1 U10.18 | length 137.3
  Top Layer w8: U10.18@2469.7,446.8 2558.2,446.8 2575,430 TP21.1@2575,405
IOUT0: D9.2 R48.1 U10.19 | length 899.5
  Top Layer w8: U10.19@2469.7,472.4 v3(2580,472.4) 2607.6,472.4 2640,440 D9.2@2640,430 ; R48.1@2676.5,1055 v3(2722.87,1055)
  Bottom Layer w8: v3(2580,472.4) 2610.03,472.4 2681,543.37 2681,1013.13 v3(2722.87,1055)
LATCH_ISO: R29.1 TP15.1 U6.14 U10.7 | length 1324
  Top Layer w8: U6.14@1014.41,442.5 1082.5,442.5 1110,470 1530,470 TP15.1@1565,435 1615,385 2090,385 2098.62,393.62 R29.1@2098.62,420 2143.1,420 2170,446.9 U10.7@2250.7,446.9
MISO: J3.5 U6.6 | length 907.9
  Top Layer w8: v3(208,682) 208,485 261,432 558.25,432 621.44,368.81 814.28,368.81 U6.6@815.59,367.5
  Bottom Layer w8: v3(208,682) 211.04,685.04 J3.5@261.42,685.04
MISO_ISO: R26.1 TP19.1 U6.11 | length 1064.1
  Top Layer w8: U6.11@1014.41,367.5 1077.5,367.5 1088.81,356.19 1333.81,356.19 1395,295 TP19.1@1650,295 R26.1@2048.5,295
MOSI: J3.7 U6.5 | length 915.2
  Top Layer w8: v3(207,721) 240,688 240,493 281.5,451.5 561.38,451.5 620.38,392.5 U6.5@815.59,392.5
  Bottom Layer w8: v3(207,721) 211.46,716.54 J3.7@261.42,716.54
MOSI_ISO: R13.2 TP12.1 U10.9 | length 1116.7
  Top Layer w8: R13.2@1173.62,380 1375,380 TP12.1@1415,340 2120,340 2175.7,395.7 U10.9@2250.7,395.7
NetC1_2: C1.2 C3.1 C5.2 C8.2 L1.2 R44.2 R45.2 TP3.1 U3.2 | length 181.7
  Bottom Layer w20: R44.2@408.5,1865 R45.2@408.5,1800 408.5,1743 v2@410,1741.5 ; v2@410,1743.42 R45.2@410,1801
  other v2: 406.5,1743.42
NetC6_1: C6.1 U1.6 | length 133.8
  Top Layer w10: U1.6@405.71,845.63 439.37,845.63 490,795 C6.1@518.5,795
NetC7_1: C7.1 D15.1 U3.6 | length 271.1
  Top Layer w15: U3.6@600,1541.57 600,1490 591.5,1481.5 C7.1@591.5,1435 591.5,1393.5 610,1375 v2(640,1375)
  Bottom Layer w15: D15.1@576.65,1375 v2(640,1375)
NetC10_1: C10.1 U3.7 | length 110.1
  Top Layer w15: U3.7@650,1541.57 650,1485 658.5,1476.5 C10.1@658.5,1435
NetC10_2: C10.2 R39.2 T1.1 U3.8 | length 156.7
  Bottom Layer w20: R39.2@721.5,1435 755,1435 775,1455 775,1526.43 v1(758.43,1543)
NetC23_1: C23.1 C24.1 FB1.1 R18.2 U7.5
NetC29_1: C29.1 U7.4 | length 99.1
  Top Layer w20: U7.4@1607.4,832.24 1642.76,832.24 1658.5,816.5 C29.1@1700,816.5
NetC35_1: C35.1 R25.1 | length 62.2
  Top Layer w10: C35.1@2045.54,1360 R25.1@2045.54,1422.19
NetC36_1: C36.1 R25.2 U9.2 | length 133.6
  Top Layer w10: U9.2@2043.05,1554.3 R25.2@2043.05,1480.69 C36.1@2103.05,1480.68
NetC39_1: C39.1 C40.1 C41.1 D5.1 D7.1 FB2.1 R20.2 | length 656.5
  Top Layer w15: 2350.04,1275 C41.1@2350.04,1330
  Top Layer w25: D5.1@1945,1355.53 D5.1@1945.53,1355 ; R20.2@1947,1262.46 1947,1353.53 D5.1@1945.53,1355 ; 2420,1275 2350.04,1275 2060,1275 1980,1355 D5.1@1945.53,1355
